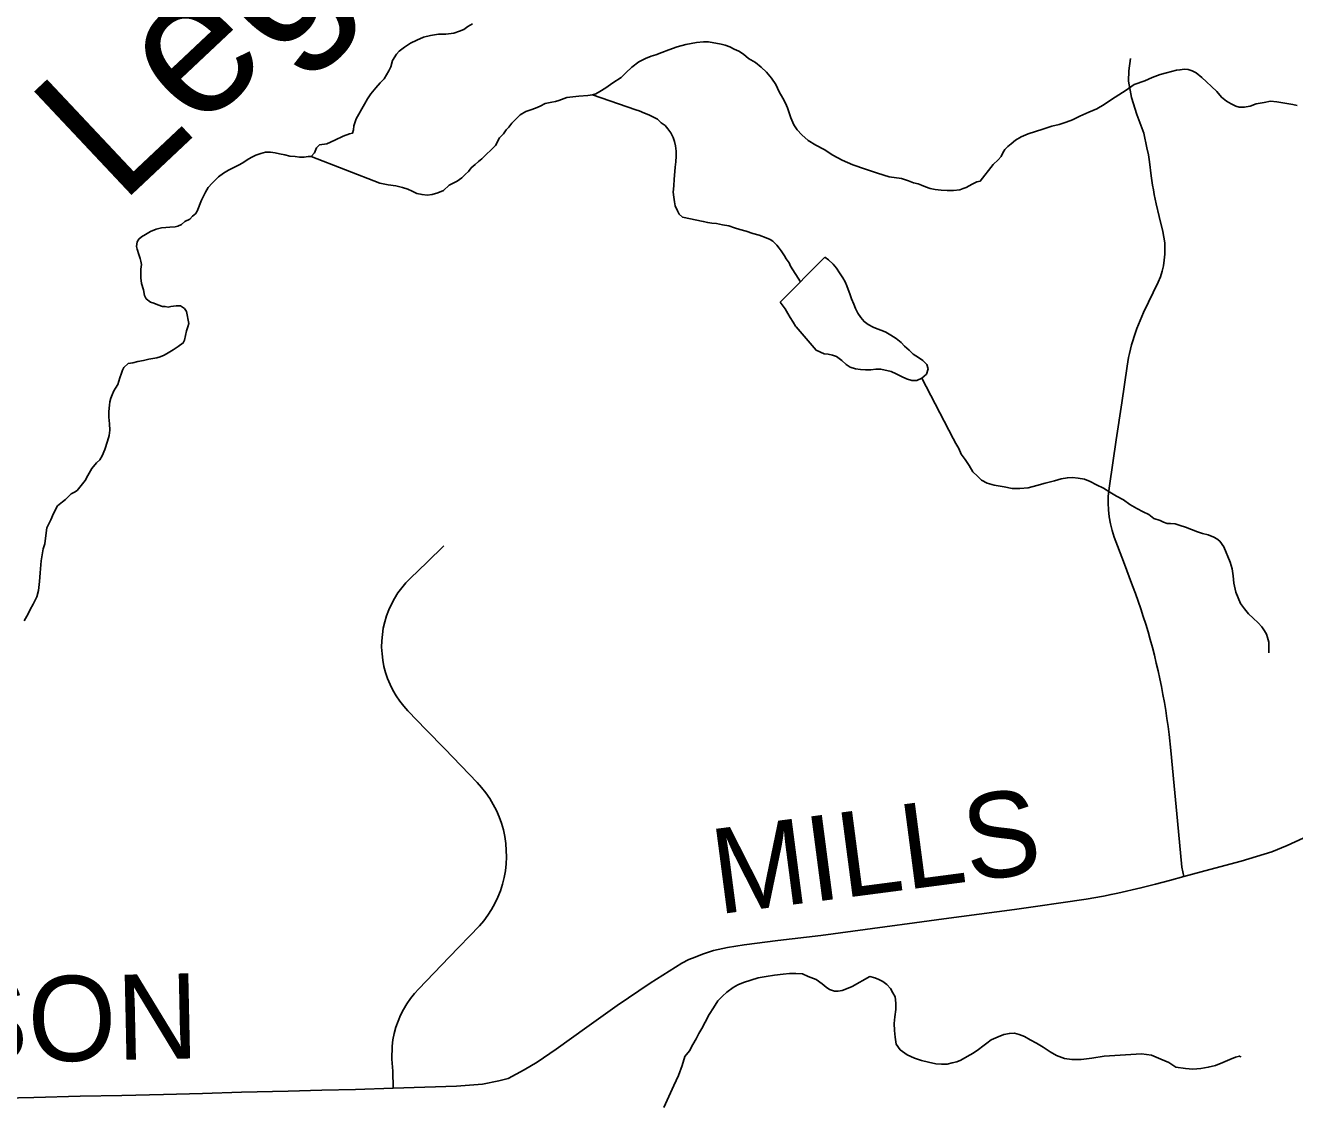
# Model space of a CAD drawing. Extents: x 103424 to 290657, y 38711 to 110967.
# Drawn here: x 120775 to 125274, y 87810 to 91629 of the extents above; entities that cross this region are included whole.
import ezdxf

# ---------------------------------------------------------------- set-up
doc = ezdxf.new("R2010")
doc.units = 0
for name, color, linetype in [('GM_X_County_Road', 7, 'Continuous'), ('GM_X_County_Road_Text', 7, 'Continuous'), ('GM_X_Minor_Lake', 7, 'Continuous'), ('GM_X_Minor_River', 7, 'Continuous'), ('GM_X_Minor_River_Text', 7, 'Continuous'), ('GM_X_Township_Road', 7, 'Continuous')]:
    doc.layers.add(name, color=color, linetype=linetype)

msp = doc.modelspace()

# ---------------------------------------------------------------- linework, layer by layer
at = {"layer": 'GM_X_County_Road'}
msp.add_lwpolyline([(120640.1, 87825), (120804.6, 87828.9), (120969.1, 87832.8), (121116.9, 87835.7), (121264.6, 87838.6), (121402.6, 87842.9), (121540.6, 87847.1), (121705.7, 87851), (121825.5, 87853.8), (121945.2, 87856.6), (122078.7, 87861.2), (122190.5, 87865), (122302.3, 87868.7), (122395, 87875.8), (122452.5, 87887.4), (122486.5, 87896.2), (122542.6, 87926), (122589, 87953.2), (122656.3, 87999.6), (122764.7, 88077.2), (122872.5, 88154.3), (122989.4, 88233.7), (123102.2, 88304.3), (123126.4, 88317), (123148.3, 88326.1), (123174.8, 88336.5), (123213.8, 88348.9), (123263.7, 88360.4), (123322.2, 88369.5), (123442.1, 88384.6), (123593.9, 88403.2), (123707.8, 88418.3), (123821.8, 88433.3), (123926.3, 88447.4), (124030.9, 88461.4), (124155.9, 88478.4), (124281, 88495.4), (124363.2, 88506.8), (124445.5, 88518.4), (124534.6, 88532), (124596.4, 88542.6), (124623.5, 88548.2), (124647.7, 88553.2), (124729, 88571.3), (124781.2, 88584.8), (124830.5, 88598.1), (124881.6, 88611.4), (124972.9, 88636.5), (125083.9, 88666.6), (125192.6, 88699.4), (125247.8, 88721.2), (125303.9, 88747.8)], dxfattribs=at)
at = {"layer": 'GM_X_Minor_Lake'}
msp.add_line((123608.9, 90807.5), (123450, 90648.2), dxfattribs=at)
for points in [[(123506.6, 90560.9), (123577.5, 90477.2), (123605.7, 90465.3), (123619.8, 90463.4), (123636, 90459.5), (123650.1, 90455.5), (123668.3, 90441.5), (123684.5, 90427.5), (123698.6, 90417.5), (123716.8, 90411.6), (123734.9, 90409.7), (123753.1, 90407.8), (123771.2, 90407.9), (123789.3, 90410.1), (123807.4, 90410.2), (123843.7, 90402.4), (123861.8, 90394.4), (123880, 90384.5), (123898.2, 90376.5), (123916.4, 90370.6), (123934.5, 90370.7), (123952.5, 90378.9), (123968.5, 90393.2), (123974.5, 90411.3), (123970.3, 90427.5), (123956.1, 90441.5), (123940, 90451.4), (123921.8, 90463.4), (123907.6, 90477.4), (123891.4, 90491.4), (123879.2, 90505.5), (123861, 90519.5), (123842.8, 90531.4), (123824.6, 90541.4), (123810.5, 90547.3), (123794.3, 90553.3), (123780.2, 90559.2), (123762, 90569.2), (123747.9, 90579.2), (123735.7, 90593.2), (123725.5, 90609.3), (123717.4, 90625.4), (123711.2, 90641.4), (123703, 90659.6), (123698.9, 90673.6), (123686.6, 90705.8), (123680.5, 90719.9), (123672.3, 90733.9), (123660.1, 90752), (123650, 90768.1), (123637.8, 90782.1), (123621.6, 90798.1), (123608.9, 90807.5)], [(123450, 90648.2), (123467.8, 90623.7), (123477.9, 90607.6), (123486.1, 90593.5), (123496.3, 90577.5), (123504.4, 90563.4), (123506.6, 90560.9)]]:
    msp.add_lwpolyline(points, dxfattribs=at)
at = {"layer": 'GM_X_Minor_River'}
for points in [[(121871.3, 91222.1), (121901.5, 91236.5), (121923.6, 91244.8), (121933.7, 91247), (121937.6, 91259.1), (121939.4, 91273.3), (121947.2, 91297.6), (121976.9, 91350.4), (121986.8, 91368.7), (121998.7, 91387), (122016.6, 91407.4), (122032.6, 91425.7), (122046.5, 91440), (122054.5, 91454.2), (122062.4, 91468.5), (122070.3, 91482.7), (122076.1, 91505), (122090, 91527.3), (122099.9, 91537.5), (122118, 91551.8), (122140, 91566.2), (122162.1, 91576.5), (122186.2, 91586.9), (122210.4, 91593.2), (122238.6, 91597.5), (122264.9, 91597.7), (122293.1, 91602.1), (122313.2, 91608.3), (122329.3, 91614.6), (122343.3, 91624.8), (122359.4, 91635)], [(121787.2, 91164.7), (122030.6, 91070.1), (122061, 91064.4), (122087.3, 91060.6), (122111.6, 91054.8), (122129.9, 91048.9), (122146.1, 91041), (122162.4, 91033), (122180.6, 91029.2), (122198.8, 91027.4), (122216.9, 91029.5), (122237.1, 91035.8), (122257.2, 91044.1), (122277.1, 91062.5), (122305.2, 91076.9), (122321.3, 91089.2), (122335.3, 91101.4), (122345.2, 91111.6), (122355.2, 91123.9), (122369.2, 91136.1), (122381.2, 91146.3), (122393.2, 91156.6), (122441.1, 91203.5), (122454.9, 91229.9), (122468.9, 91244.2), (122478.9, 91258.4), (122488.8, 91268.6), (122498.8, 91282.9), (122512.7, 91297.2), (122528.7, 91311.5), (122548.8, 91323.8), (122566.9, 91330), (122583, 91336.2), (122599.1, 91342.5), (122617.1, 91352.7), (122641.3, 91357), (122653.4, 91359.2), (122665.5, 91363.3), (122693.6, 91373.7), (122736, 91378.2), (122768.3, 91380.5), (122784.4, 91382.7), (122796.5, 91386.8), (122810.5, 91395.1), (122832.6, 91407.4), (122856.6, 91425.8), (122886.7, 91444.3), (122902.7, 91460.6), (122924.7, 91481.1), (122948.7, 91499.5), (122972.8, 91511.8), (122992.9, 91520.1), (123009, 91524.3), (123031.1, 91532.6), (123055.2, 91543), (123085.4, 91553.4), (123115.6, 91561.7), (123153.9, 91568.2), (123178.1, 91570.4), (123196.3, 91570.6), (123240.8, 91563), (123255, 91559.1), (123271.2, 91553.2), (123287.5, 91545.3), (123303.7, 91537.3), (123320, 91527.4), (123338.3, 91511.4), (123362.7, 91497.5), (123383.1, 91481.6), (123401.5, 91463.6), (123419.9, 91441.5), (123434.3, 91419.4), (123446.8, 91393.3), (123459.1, 91371.2), (123469.5, 91353.1), (123475.7, 91337), (123482, 91318.9), (123488.2, 91300.8), (123498.6, 91276.6), (123510.9, 91258.6), (123527.3, 91240.6), (123549.8, 91220.6), (123576.2, 91204.7), (123606.7, 91188.8), (123637.2, 91168.9), (123669.7, 91151), (123708.3, 91135.3), (123752.9, 91119.5), (123795.5, 91105.8), (123836, 91092.1), (123880.5, 91086.5), (123904.9, 91078.6), (123923.1, 91070.7), (123939.3, 91066.9), (123951.5, 91062.9), (123965.7, 91057), (123981.9, 91051.1), (124000.2, 91047.3), (124020.4, 91045.4), (124042.6, 91043.6), (124064.8, 91043.9)], [(124064.8, 91043.9), (124087, 91046.1), (124099.1, 91050.3), (124109.1, 91054.4), (124131.2, 91066.7), (124147.3, 91075), (124159.4, 91077.1), (124205.1, 91136.2), (124223.1, 91152.5), (124233.1, 91164.7), (124239, 91176.9), (124246.9, 91189.1), (124256.9, 91199.3), (124268.9, 91209.5), (124284.9, 91221.8), (124305, 91234.1), (124329.1, 91244.5), (124355.3, 91252.8), (124381.4, 91261.2), (124413.6, 91271.6), (124439.8, 91277.9), (124463.9, 91286.2), (124486.1, 91294.5), (124512.2, 91306.9), (124544.3, 91321.4), (124572.5, 91333.8), (124598.5, 91348.2), (124624.6, 91366.6), (124650.6, 91383), (124676.7, 91399.4), (124704.8, 91419.9), (124743, 91432.4), (124769.1, 91444.8), (124797.3, 91455.2), (124819.4, 91461.5), (124837.5, 91465.7), (124855.7, 91469.9), (124867.8, 91472.1), (124881.9, 91474.2), (124896, 91472.4), (124910.2, 91468.4), (124924.4, 91460.5), (124944.8, 91444.5), (124961.2, 91428.5), (124979.5, 91412.6), (124997.9, 91394.6), (125014.3, 91374.5), (125032.6, 91360.6), (125048.9, 91350.6), (125065.2, 91342.7), (125077.3, 91338.8), (125095.5, 91339), (125115.7, 91343.2), (125137.8, 91351.5), (125166, 91355.8), (125188.2, 91360.1), (125210.4, 91358.3), (125267.1, 91348.7), (125283.3, 91344.9)], [(122784.4, 91382.7), (122938.5, 91329.7), (122950.7, 91325.7), (122969, 91317.8), (122985.2, 91311.9), (123001.4, 91304), (123015.7, 91296.1), (123027.9, 91284.1), (123042.2, 91274.1), (123052.4, 91262.1), (123062.7, 91248.1), (123071, 91232), (123075.2, 91217.9), (123079.4, 91201.8), (123081.6, 91183.6), (123081.8, 91165.4), (123080, 91145.2), (123078.2, 91127), (123076.4, 91110.8), (123074.7, 91084.5), (123072.9, 91060.3), (123071.2, 91038), (123073.4, 91019.9), (123075.6, 91003.7), (123077.8, 90989.6), (123086.1, 90971.5), (123092.3, 90959.5), (123104.5, 90949.5), (123177.4, 90934), (123193.6, 90930.1), (123207.8, 90928.3), (123224, 90926.4), (123246.2, 90922.6), (123268.5, 90918.8), (123288.8, 90910.9), (123307, 90905), (123329.3, 90899.2), (123353.6, 90891.3), (123375.9, 90885.5), (123400.3, 90875.6), (123414.5, 90869.7), (123424.6, 90863.7), (123438.9, 90849.8), (123447.1, 90839.7), (123453.3, 90829.7), (123465.6, 90811.6), (123471.8, 90801.6), (123482.1, 90787.5), (123486.3, 90775.5), (123521.8, 90720.2)], [(121074.2, 90294.9), (121078.1, 90307.1), (121082, 90319.3), (121087.9, 90333.4), (121093.9, 90343.6), (121101.8, 90355.8), (121109.6, 90380.1), (121115.5, 90396.4), (121119.4, 90406.5), (121123.3, 90416.6), (121139.3, 90430.9), (121155.4, 90433.1), (121173.6, 90437.3), (121193.7, 90441.6), (121211.8, 90445.8), (121226, 90448), (121240.1, 90450.1), (121252.1, 90454.3), (121266.2, 90460.5), (121280.2, 90468.7), (121298.3, 90479), (121316.3, 90491.3), (121334.4, 90503.6), (121338.3, 90513.7), (121342.1, 90529.9), (121346, 90546.1), (121349.9, 90560.3), (121353.8, 90572.5), (121345.2, 90614.8), (121339, 90624.9), (121324.8, 90634.8), (121308.6, 90634.6), (121290.4, 90632.5), (121280.4, 90630.3), (121270.3, 90632.3), (121260.2, 90632.2), (121243.9, 90638), (121229.7, 90644), (121217.6, 90647.9), (121203.3, 90659.9), (121197.1, 90671.9), (121192.8, 90692.1), (121186.5, 90714.3), (121184.2, 90734.4), (121184.1, 90746.6), (121183.9, 90764.7), (121185.7, 90780.9), (121183.6, 90793), (121181.4, 90803.1), (121177.2, 90817.2), (121171, 90835.3), (121168.8, 90845.4), (121170.6, 90861.6), (121176.6, 90871.7), (121186.6, 90879.9), (121200.6, 90888.1), (121218.7, 90898.4), (121238.8, 90906.7), (121256.9, 90910.9), (121273, 90913.1), (121287.2, 90913.2), (121305.3, 90915.4), (121315.4, 90917.6), (121327.5, 90923.7), (121339.5, 90934), (121357.5, 90942.2), (121367.5, 90952.4), (121377.5, 90960.6), (121383.5, 90970.8), (121399.2, 91009.3), (121405.1, 91021.5), (121413, 91037.7), (121422.9, 91054), (121436.8, 91070.3), (121458.8, 91092.7), (121476.8, 91105), (121494.9, 91115.3), (121508.9, 91123.5), (121523, 91129.7), (121535.1, 91135.9), (121549.1, 91144.1), (121561.1, 91152.3), (121575.2, 91160.6), (121591.2, 91168.8), (121609.3, 91175), (121625.4, 91179.2), (121643.6, 91179.4), (121659.8, 91177.6), (121676, 91173.7), (121694.2, 91169.8), (121712.4, 91166), (121730.6, 91164.1), (121746.8, 91162.3), (121763, 91162.4), (121777.1, 91164.6), (121787.2, 91164.7), (121799.2, 91176.9), (121807, 91195.2), (121817, 91205.4), (121843.2, 91209.7), (121871.3, 91222.1)], [(123952.5, 90378.9), (124062.9, 90165), (124073.2, 90146.9), (124083.5, 90128.8), (124091.8, 90108.7), (124106.2, 90090.7), (124120.6, 90068.6), (124133, 90046.5), (124149.3, 90030.5), (124163.6, 90016.5), (124183.9, 90006.6), (124208.3, 89998.8), (124244.7, 89993.1), (124273, 89987.3), (124299.3, 89987.5), (124329.5, 89989.9), (124359.7, 89998.2), (124389.9, 90006.6), (124422.2, 90015), (124446.3, 90021.3), (124468.5, 90025.6), (124486.7, 90025.8), (124506.9, 90023.9), (124529.1, 90020.1), (124549.4, 90012.2), (124571.8, 90000.3), (124596.2, 89988.5), (124618.5, 89974.6), (124642.9, 89960.6), (124667.3, 89946.8), (124689.7, 89930.8), (124714.1, 89916.9), (124736.5, 89905), (124756.8, 89895.1), (124775.1, 89881.2), (124797.5, 89873.3), (124809.6, 89867.4), (124821.8, 89863.4), (124833.9, 89863.5), (124850.1, 89861.7), (124868.3, 89855.8), (124886.6, 89849.9), (124908.9, 89842.1), (124929.2, 89834.2), (124947.4, 89828.3), (124967.7, 89822.5), (124988, 89814.6), (124998.2, 89808.6), (125008.4, 89800.6), (125022.7, 89780.6), (125045.6, 89726.3), (125051.9, 89702.1), (125056.2, 89677.9), (125058.6, 89651.6), (125065, 89619.4), (125073.3, 89599.2), (125081.6, 89579.1), (125096, 89561.1), (125110.3, 89543), (125126.7, 89527.1), (125145, 89511.1), (125157.3, 89497.1), (125167.6, 89483), (125173.8, 89471), (125177.9, 89458.9), (125182.2, 89442.8), (125182.4, 89424.6), (125182.5, 89414.5), (125182.6, 89404.4)], [(120770.2, 89518.1), (120784, 89542.5), (120791.9, 89558.8), (120801.8, 89577), (120815.7, 89603.4), (120821.5, 89625.7), (120825.1, 89658.1), (120826.8, 89688.4), (120830.3, 89730.9), (120837.9, 89773.4), (120843.8, 89791.6), (120845.5, 89811.8), (120851.2, 89848.3), (120865, 89876.7), (120874.8, 89899), (120888.7, 89925.4), (120906.7, 89939.7), (120916.7, 89947.9), (120926.7, 89958.1), (120936.6, 89968.3), (120948.7, 89974.5), (120958.7, 89980.6), (120986.6, 90015.3), (120996.5, 90033.5), (121010.3, 90057.9), (121026.2, 90078.3), (121038.3, 90088.5), (121046.2, 90102.7), (121056, 90125), (121065.7, 90155.4), (121071.6, 90175.7), (121073.4, 90193.9), (121073.1, 90216.1), (121070.8, 90240.3), (121070.6, 90260.5), (121072.4, 90282.8), (121074.2, 90294.9)], [(123038.2, 87793.2), (123055.9, 87831.7), (123073.6, 87870.3), (123089.4, 87906.8), (123103.1, 87941.3), (123112.8, 87973.7), (123128.7, 87994.1), (123140.6, 88016.4), (123152.5, 88036.7), (123162.4, 88055), (123172.3, 88073.3), (123184.1, 88095.6), (123198, 88122), (123213.8, 88146.4), (123229.7, 88170.8), (123245.7, 88187.2), (123261.7, 88201.4), (123283.7, 88217.8), (123299.7, 88228.1), (123319.8, 88236.4), (123346, 88244.7), (123372.2, 88253), (123400.4, 88257.4), (123430.6, 88261.7), (123460.9, 88266.1), (123483.1, 88268.3), (123505.3, 88268.5), (123529.5, 88266.7), (123549.8, 88256.8), (123578.2, 88247), (123598.6, 88231.1), (123612.9, 88219.1), (123625.1, 88211.1), (123643.3, 88205.2), (123655.5, 88205.4), (123669.6, 88207.5), (123685.7, 88213.7), (123705.8, 88222), (123768, 88257), (123786.2, 88253.1), (123800.4, 88247.2), (123814.6, 88239.3), (123828.9, 88229.3), (123841.2, 88215.3), (123849.4, 88199.2), (123857.7, 88185.1), (123859.9, 88162.9), (123860.2, 88140.7), (123856.5, 88114.4), (123854.7, 88090.2), (123855, 88065.9), (123857.3, 88041.7), (123861.6, 88017.5), (123876, 87997.4), (123900.4, 87979.5), (123926.8, 87967.7), (123951.2, 87959.8), (123975.5, 87954), (124001.8, 87948.2), (124022, 87946.4), (124042.2, 87946.6), (124060.3, 87950.8), (124076.4, 87955), (124090.5, 87961.2), (124112.6, 87973.5), (124134.7, 87985.9), (124152.7, 87998.2), (124168.7, 88010.5), (124182.7, 88020.7), (124198.7, 88033), (124222.9, 88043.3), (124243, 88051.6), (124263.1, 88055.8), (124281.3, 88056), (124297.5, 88052.1), (124315.8, 88044.2), (124336.1, 88032.3), (124358.5, 88020.4), (124382.9, 88006.5), (124407.3, 87990.6), (124429.7, 87976.7), (124458, 87966.9), (124484.3, 87963.1)], [(124484.3, 87963.1), (124516.7, 87963.4), (124555, 87967.8), (124599.3, 87974.3), (124730.5, 87983.7), (124766.9, 87978), (124799.4, 87964.2), (124827.8, 87952.4), (124852.2, 87936.4), (124886.6, 87930.7), (124912.9, 87929), (124941.2, 87931.3), (124967.4, 87935.6), (124993.6, 87941.9), (125019.7, 87952.2), (125043.8, 87962.6), (125063.9, 87970.9), (125078, 87975), (125082.1, 87973.1), (125082, 87975.1)]]:
    msp.add_lwpolyline(points, dxfattribs=at)
at = {"layer": 'GM_X_Township_Road'}
for points in [[(124881.6, 88611.4), (124874.5, 88644.5), (124858.8, 88808.8), (124846.8, 88933.7), (124834.8, 89058.6), (124828.8, 89115.5), (124825.1, 89143.9), (124821.3, 89172.2), (124817, 89200.5), (124812.2, 89228.7), (124807.2, 89256.8), (124801.9, 89284.9), (124796.2, 89313), (124790.2, 89340.9), (124783.6, 89368.7), (124776.8, 89396.5), (124769.6, 89424.2), (124762, 89451.7), (124754.2, 89479.2), (124745.9, 89506.6), (124737.4, 89533.9), (124728.3, 89561), (124719.3, 89588.1), (124709.5, 89615), (124699.4, 89641.8), (124666.7, 89728.4), (124634, 89814.9), (124626.8, 89838.5), (124621, 89862.4), (124616.7, 89886.7), (124614.2, 89911.2), (124613, 89935.7), (124613.5, 89960.4), (124617.3, 89997.1), (124641.5, 90160.4), (124660.8, 90290.7), (124680.2, 90421), (124682.7, 90436.2), (124685.4, 90451.3), (124688.5, 90466.4), (124692, 90481.4), (124695.8, 90496.2), (124700.1, 90511), (124704.6, 90525.7), (124709.4, 90540.3), (124714.7, 90554.7), (124720, 90569.1), (124726, 90583.3), (124732.1, 90597.4), (124738.7, 90611.3), (124790.3, 90718.9), (124797.9, 90737.9), (124804.2, 90757.3), (124808.7, 90777.1), (124812, 90797.2), (124814, 90817.5), (124813.3, 90858.2), (124810.8, 90878.4), (124806.8, 90898.3), (124794.2, 90951.2), (124783.4, 90996.4), (124779.9, 91012.7), (124776.4, 91029.1), (124773.1, 91045.6), (124770.3, 91062.1), (124767.8, 91078.7), (124765.6, 91095.3), (124759.3, 91145.2), (124755.5, 91170), (124750.2, 91194.5), (124739.3, 91246.8), (124714.3, 91312.7), (124695.3, 91373.9), (124684.8, 91431.7), (124686.4, 91467.5), (124691.5, 91511.6)], [(122078.7, 87861.2), (122077, 87921.3), (122073.3, 87964.4), (122074.6, 88010.2), (122077.6, 88032.9), (122082.2, 88055.3), (122088.2, 88077.4), (122095.8, 88099.1), (122104.6, 88120.2), (122115, 88140.6), (122126.8, 88160.3), (122139.6, 88179.2), (122153.7, 88197.1), (122169.1, 88214.1), (122276.5, 88325.4), (122383.9, 88436.7), (122399.6, 88455.2), (122414.1, 88474.8), (122427.3, 88495.3), (122439.1, 88516.6), (122449.4, 88538.6), (122458.3, 88561.2), (122465.8, 88584.4), (122471.6, 88608.1), (122476.1, 88632), (122478.9, 88656.2), (122479.9, 88680.5), (122477.7, 88729.1), (122474.2, 88753.2), (122468.9, 88777), (122462.4, 88800.4), (122454.1, 88823.3), (122444.6, 88845.7), (122433.2, 88867.4), (122420.9, 88888.2), (122407.1, 88908.3), (122392, 88927.4), (122375.6, 88945.5), (122261, 89064.2), (122195.9, 89131.6), (122130.8, 89199), (122115.7, 89215.8), (122101.6, 89233.7), (122088.8, 89252.4), (122077.5, 89272), (122067.4, 89292.4), (122058.6, 89313.3), (122051.3, 89334.8), (122045.8, 89356.7), (122041.5, 89379.1), (122038.8, 89401.6), (122037.5, 89424.3), (122038, 89446.9), (122040, 89469.5), (122043.3, 89492), (122048.4, 89514.1), (122054.9, 89535.9), (122063, 89557.1), (122072.3, 89577.8), (122083.2, 89597.7), (122095.2, 89616.9), (122108.6, 89635.1), (122123.2, 89652.5), (122139.1, 89668.8), (122198.8, 89726.5), (122258.5, 89784.2)]]:
    msp.add_lwpolyline(points, dxfattribs=at)

# ---------------------------------------------------------------- texts
at = {"layer": 'GM_X_County_Road_Text'}
for s, rotation, p in [('MILLS', 7.4514, (123229.4, 88477.3)), ('WILSON', 1.2256, (119799.4, 87933.4))]:
    msp.add_text(s, height=301.87, rotation=rotation, dxfattribs=at).set_placement(p)
at = {"layer": 'GM_X_Minor_River_Text'}
msp.add_text('Legend', height=503.49, rotation=43.245, dxfattribs=at).set_placement((121110.4, 90990.1))

doc.saveas('drawing.dxf')
